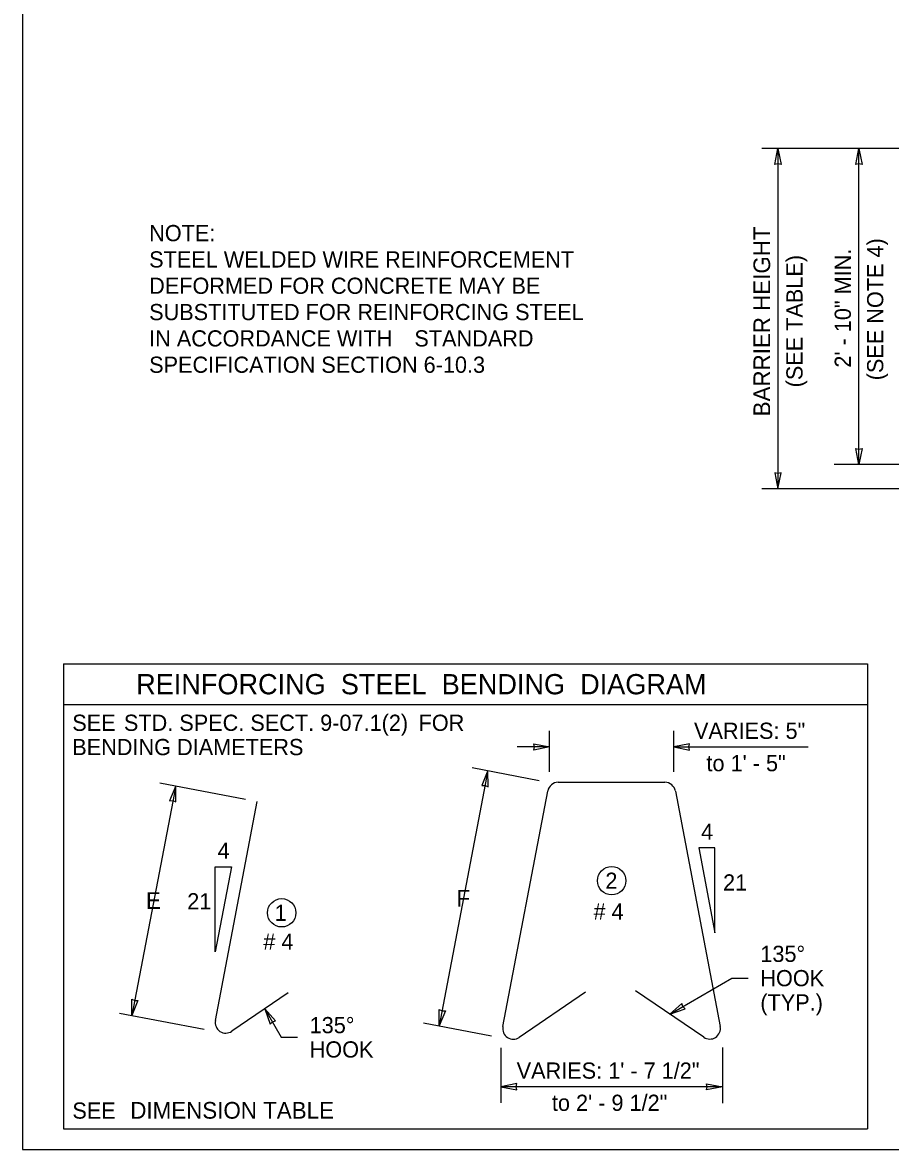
# Model space of a CAD drawing. Extents: x 99862 to 103151, y 100000 to 102076.
# Drawn here: x 99862 to 100719, y 100000 to 101112 of the extents above; entities that cross this region are included whole.
import ezdxf

# ---------------------------------------------------------------- set-up
doc = ezdxf.new("R2010")
doc.units = 0
for name, color, linetype in [('Level 1', 7, 'Continuous'), ('Level 10', 7, 'Continuous'), ('Level 15', 7, 'Continuous'), ('Level 16', 7, 'Continuous'), ('Level 20', 7, 'Continuous'), ('Level 40', 7, 'Continuous'), ('Level 60', 7, 'Continuous')]:
    doc.layers.add(name, color=color, linetype=linetype)

msp = doc.modelspace()

# ---------------------------------------------------------------- linework, layer by layer
at = {"layer": 'Level 1'}
msp.add_lwpolyline([(99862, 99999.5), (103151, 99999.5), (103151, 102075.5), (99862, 102075.5)], close=True, dxfattribs=at)
at = {"layer": 'Level 10'}
for p, q in [((100336.2, 100120.9), (100380.6, 100353.5)), ((100390.9, 100362.1), (100496.3, 100362.1)), ((100506.6, 100353.5), (100550.9, 100121)), ((100052.4, 100126.9), (100093.6, 100343.3)), ((100124.4, 100154.2), (100068.6, 100116.2)), ((100417.8, 100154.7), (100352.5, 100110.2)), ((100534.7, 100110.3), (100467.3, 100156.1))]:
    msp.add_line(p, q, dxfattribs=at)
for centre, start, end in [((100390.9, 100351.6), 90, 169.2157), ((100496.3, 100351.6), 10.7843, 90), ((100062.7, 100124.9), 169.2157, 304.2157), ((100346.6, 100118.9), 169.2157, 304.2157), ((100540.6, 100119), 235.7843, 10.7843)]:
    msp.add_arc(centre, 10.5, start, end, dxfattribs=at)
at = {"layer": 'Level 15'}
for p, q in [((100975.7, 100988), (100591.9, 100988)), ((100607.9, 100988), (100607.9, 100652)), ((100687.9, 100676), (100687.9, 100988)), ((100911.9, 100652), (100591.9, 100652)), ((100382.4, 100372.4), (100382.4, 100413)), ((100505, 100372.3), (100505, 100413)), ((100382.4, 100397), (100350.4, 100397)), ((100505, 100397), (100637.6, 100397)), ((100305.8, 100376.6), (100372.1, 100364)), ((100321.5, 100373.6), (100273.5, 100121.6)), ((100013.2, 100358.7), (99970, 100131.8)), ((99997.5, 100361.7), (100082, 100345.6)), ((100501, 100133.2), (100562.5, 100168.7)), ((100562.5, 100168.7), (100578.5, 100168.7)), ((99957.8, 100134.2), (100041.2, 100118.3)), ((100101.3, 100138.4), (100117.5, 100110.3)), ((100257.8, 100124.6), (100325.2, 100111.8)), ((100117.5, 100110.3), (100133.5, 100110.3)), ((100334.4, 100100), (100334.4, 100045.4)), ((100553, 100100.2), (100553, 100045.3)), ((100553, 100061.3), (100334.4, 100061.4))]:
    msp.add_line(p, q, dxfattribs=at)
for points in [[(100607.9, 100988), (100611, 100972.3), (100607.9, 100973), (100604.9, 100972.3)], [(100687.9, 100988), (100691, 100972.2), (100687.9, 100973), (100684.8, 100972.2)], [(100687.9, 100676), (100684.8, 100691.7), (100687.9, 100691), (100691, 100691.7)], [(100607.9, 100652), (100611, 100667.7), (100607.9, 100667), (100604.8, 100667.7)], [(100382.4, 100397), (100366.7, 100393.9), (100367.4, 100397), (100366.7, 100400.1)], [(100505, 100397), (100520.7, 100393.9), (100520, 100397), (100520.7, 100400.1)], [(100321.5, 100373.6), (100315.5, 100358.8), (100318.7, 100358.9), (100321.6, 100357.6)], [(100013.2, 100358.7), (100007.2, 100343.9), (100010.4, 100344), (100013.3, 100342.7)], [(99970, 100131.9), (99969.9, 100147.9), (99972.8, 100146.6), (99976, 100146.7)], [(100501, 100133.2), (100516.2, 100138.4), (100514, 100140.7), (100513.1, 100143.7)], [(100101.3, 100138.4), (100106.5, 100123.3), (100108.8, 100125.4), (100111.8, 100126.4)], [(100273.5, 100121.6), (100273.4, 100137.7), (100276.3, 100136.4), (100279.5, 100136.5)], [(100334.4, 100061.4), (100350.1, 100058.3), (100349.4, 100061.4), (100350.1, 100064.5)], [(100553, 100061.3), (100537.3, 100058.3), (100538, 100061.3), (100537.3, 100064.4)]]:
    msp.add_lwpolyline(points, close=True, dxfattribs=at)
for points in [[(100545.7, 100213.3), (100545.7, 100297.3), (100529.7, 100297.3), (100545.7, 100213.3)], [(100052.3, 100194.6), (100052.3, 100278.6), (100068.3, 100278.6), (100052.3, 100194.6)]]:
    msp.add_lwpolyline(points, dxfattribs=at)
at = {"layer": 'Level 16'}
msp.add_lwpolyline([(100928.5, 100676), (100663.4, 100676)], dxfattribs=at)
at = {"layer": 'Level 20'}
for centre in [(100443.7, 100264.9), (100117.9, 100233.2)]:
    msp.add_circle(centre, 14, dxfattribs=at)
at = {"layer": 'Level 40'}
for p, q in [((99902.4, 100479), (100696.4, 100479)), ((99902.4, 100479), (99902.4, 100019.9)), ((100696.4, 100479), (100696.4, 100019.9)), ((99902.4, 100439), (100696.4, 100439)), ((99902.4, 100019.9), (100696.4, 100019.9))]:
    msp.add_line(p, q, dxfattribs=at)
at = {"layer": 'Level 60'}
msp.add_line((99862, 99999.5), (99862, 99999.5), dxfattribs=at)

# ---------------------------------------------------------------- texts
at = {"layer": 'Level 15'}
for s, p in [('E', (99983.9, 100237)), ('F', (100290.5, 100239.4))]:
    msp.add_text(s, height=16.5, dxfattribs=at).set_placement(p)
at = {"layer": 'Level 20'}
for s, height, p in [('NOTE:', 16, (99987, 100896.5)), ('STEEL WELDED WIRE REINFORCEMENT ', 16, (99987, 100870.5)), ('DEFORMED FOR CONCRETE MAY BE ', 16, (99987, 100844.5)), ('SUBSTITUTED FOR REINFORCING STEEL', 16, (99987, 100818.5)), ('IN ACCORDANCE WITH ', 16, (99987, 100792.5)), ('STANDARD ', 16, (100248.9, 100792.5)), ('SPECIFICATION SECTION 6-10.3', 16, (99987, 100766.5)), ('REINFORCING  STEEL  BENDING  DIAGRAM', 20, (99974.2, 100449)), ('SEE ', 16, (99911.1, 100412.9)), ('STD. SPEC. SECT. 9-07.1(2)', 16, (99962.1, 100412.9)), (' FOR ', 16, (100247.1, 100412.9)), ('VARIES: 5" ', 16, (100525, 100405)), ('BENDING DIAMETERS', 16, (99911.1, 100388.9)), ('to 1\' - 5"', 16, (100537.3, 100373)), ('4', 16, (100532, 100305.3)), ('2', 16, (100437.5, 100256.9)), ('21', 16, (100553.7, 100255.2)), ('1', 16, (100110.9, 100225.2)), ('# 4', 16, (100425.8, 100226.6)), ('# 4', 16, (100099.7, 100196.7)), ('135° ', 16, (100590.5, 100184.7)), ('HOOK', 16, (100590.5, 100160.7)), ('(TYP.)', 16, (100590.5, 100136.7)), ('135°', 16, (100145.5, 100114.3)), ('HOOK', 16, (100145.5, 100090.3)), ('to 2\' - 9 1/2"', 16, (100384.7, 100037.6)), ('SEE  ', 16, (99911.2, 100029.9)), ('DIMENSION TABLE', 16.5, (99968.4, 100029.9))]:
    msp.add_text(s, height=height, dxfattribs=at).set_placement(p)
for s, height, rotation, p in [('BARRIER HEIGHT', 16.5, 90, (100600.2, 100723.5)), ('(SEE NOTE 4)', 16, 90, (100711.9, 100759.1)), ('2\' - 10" MIN.', 16, 90, (100679.9, 100771.6)), ('(SEE TABLE)', 16, 90, (100632.2, 100752.1)), ('4', 16, 360, (100054.6, 100286.6)), ('21', 16, 360, (100024.6, 100236.6)), ('VARIES: 1\' - 7 1/2"', 16, 360, (100349.9, 100069.4))]:
    msp.add_text(s, height=height, rotation=rotation, dxfattribs=at).set_placement(p)

doc.saveas('drawing.dxf')
